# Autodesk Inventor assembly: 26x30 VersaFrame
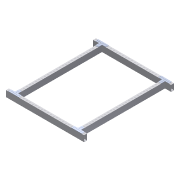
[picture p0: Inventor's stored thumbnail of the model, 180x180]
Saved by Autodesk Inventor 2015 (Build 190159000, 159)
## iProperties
Created: 2014-12
Part Number: 26x30 VersaFrame
Document SubType Name: Assembly
Designer: Nemo
Author: Nemo
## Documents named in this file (4)
- H:\Nemo\Documents\Robotics\CAD Files\COTS Parts\VersaFrame\26x30 Frame\26x30 VersaFrame 12-20-14.iam
- H:\Nemo\Documents\Robotics\CAD Files\COTS Parts\VersaFrame\26x30 Frame\VersaFrame End Rail 12-20-14.ipt
- H:\Nemo\Documents\Robotics\CAD Files\COTS Parts\VersaFrame\26x30 Frame\VersaFrame Side Rail 12-20-14.ipt
- H:\Nemo\Documents\Robotics\CAD Files\COTS Parts\VersaFrame\VersaFrame VersaChassis Gusset.ipt
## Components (8 placed, 5 different names)
1. VersaFrame End Rail: Front — Mate:1, Flush:1, Flush:2, Flush:3, Flush:8, Flush:9, Mate:6, Flush:14, Mate:7, Flush:16, Flush:18, Flush:19, Mate:9
2. VersaFrame End Rail: Back — Mate:1, Flush:2, Mate:4, Flush:10, Mate:5, Flush:13, Mate:10
3. VersaFrame Side Rail: Right — Flush:18, Mate:8, Flush:19, Flush:20, Flush:21
4. VersaFrame Side Rail: Left — Flush:7, Flush:8, Flush:9, Flush:12, Flush:17, Mate:9, Mate:10
5. VersaFrame VersaChassis Gusset:1 — Mate:7, Flush:16, Flush:17
6. VersaFrame VersaChassis Gusset:2 — Mate:6, Flush:14, Flush:20
7. VersaFrame VersaChassis Gusset:3 — Mate:5, Flush:12, Flush:13
8. VersaFrame VersaChassis Gusset:4 — Mate:4, Flush:10, Flush:21
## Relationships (24: Flush 16, Mate 8)
- Mate:1: VersaFrame End Rail: Front ↔ VersaFrame End Rail: Back
- Flush:1: VersaFrame End Rail: Front
- Flush:2: VersaFrame End Rail: Front ↔ VersaFrame End Rail: Back
- Flush:3: VersaFrame End Rail: Front
- Flush:7: VersaFrame Side Rail: Left
- Flush:8: VersaFrame End Rail: Front ↔ VersaFrame Side Rail: Left
- Flush:9: VersaFrame End Rail: Front ↔ VersaFrame Side Rail: Left
- Mate:4: VersaFrame End Rail: Back ↔ VersaFrame VersaChassis Gusset:4
- Flush:10: VersaFrame End Rail: Back ↔ VersaFrame VersaChassis Gusset:4
- Mate:5: VersaFrame End Rail: Back ↔ VersaFrame VersaChassis Gusset:3
- Flush:12: VersaFrame Side Rail: Left ↔ VersaFrame VersaChassis Gusset:3
- Flush:13: VersaFrame End Rail: Back ↔ VersaFrame VersaChassis Gusset:3
- Mate:6: VersaFrame End Rail: Front ↔ VersaFrame VersaChassis Gusset:2
- Flush:14: VersaFrame End Rail: Front ↔ VersaFrame VersaChassis Gusset:2
- Mate:7: VersaFrame End Rail: Front ↔ VersaFrame VersaChassis Gusset:1
- Flush:16: VersaFrame End Rail: Front ↔ VersaFrame VersaChassis Gusset:1
- Flush:17: VersaFrame Side Rail: Left ↔ VersaFrame VersaChassis Gusset:1
- Flush:18: VersaFrame End Rail: Front ↔ VersaFrame Side Rail: Right
- Mate:8: VersaFrame Side Rail: Right
- Flush:19: VersaFrame End Rail: Front ↔ VersaFrame Side Rail: Right
- Mate:9: VersaFrame End Rail: Front ↔ VersaFrame Side Rail: Left
- Mate:10: VersaFrame End Rail: Back ↔ VersaFrame Side Rail: Left
- Flush:20: VersaFrame Side Rail: Right ↔ VersaFrame VersaChassis Gusset:2
- Flush:21: VersaFrame Side Rail: Right ↔ VersaFrame VersaChassis Gusset:4
## Named parameters: SideRailOffset = 50.8 mm, CenterDrop = 3.175 mm
